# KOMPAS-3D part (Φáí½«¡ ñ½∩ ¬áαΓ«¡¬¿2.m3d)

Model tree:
1. Эскиз:1
2. Операция выдавливания:1
     Толщина стенки 2 = 6; Расстояние 1 = 0.6
3. Эскиз:2
4. Операция выдавливания:2
     Толщина стенки 1 = 12; Толщина стенки 2 = 12; Расстояние 1 = 0.6; Расстояние 2 = 0.6
5. Эскиз:3
6. Операция выдавливания:3
     Толщина стенки 1 = 12; Толщина стенки 2 = 12; Расстояние 1 = 0.6; Расстояние 2 = 0.6
7. Эскиз:4
8. Операция выдавливания:4
     Толщина стенки 1 = 35; Толщина стенки 2 = 35; Расстояние 1 = 0.6; Расстояние 2 = 0.6
9. Эскиз:5
10. Вырезать элемент выдавливания:1
     Расстояние 1 = 10
11. Эскиз:6
12. Вырезать элемент выдавливания:2
     Расстояние 1 = 10
